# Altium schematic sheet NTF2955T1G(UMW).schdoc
size 127 x 101 mm
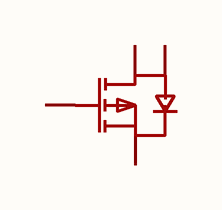
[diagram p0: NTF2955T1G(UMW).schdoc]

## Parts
Q?  ntf2955t1g(umw)  [SOT-223-3_L6.4-W3.5-P2.30-LS7.0-BR]  (value not drawn)

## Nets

Not connected (* = marked no-connect by the designer): Q? 1(G) 2(D) 3(S) 4(D)

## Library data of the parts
Q? = ntf2955t1g(umw): 数量:1个P沟道;漏源电压(Vdss):60V;连续漏极电流(Id):7A;导通电阻(RDS(on)):55mΩ@10V；65mΩ@4.5V;耗散功率(Pd):10.4W;阈值电压(Vgs(th)):2.5V;; Manufacturer: UMW(友台半导体); AddInBom: yes; ModelId: 6654433eca7b4e7f8ee05e27058a22e4; ModelTransform: 251.968,275.59,0,90,0,0,-3.937,0,0; Number: 1个P沟道; Drain to Source Voltage: 60V; Current - Continuous Drain(Id): 7A; Pd - Power Dissipation: 10.4W; Gate Threshold Voltage (Vgs(th)): 2.5V; Gate Charge(Qg): 38nC@10V; Input Capacitance(Ciss): 1.5nF; Reverse Transfer Capacitance (Crss@Vds): 150pF; Output Capacitance(Coss): 200pF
